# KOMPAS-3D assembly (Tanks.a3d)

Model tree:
1. Plane XY
2. Plane ZX
3. Plane ZY
4. X Axis
5. Y Axis
6. Z Axis
7. Origin
8. Polyline:1
9. Polyline:2
10. Polyline:3
11. Polyline:4
12. Polyline:5
13. Polyline:7
14. Polyline:8
15. Path 1
16. Path 2
17. Path 3
18. Path 4  (labels: C:\Program Files\ASCON\KOMPAS-3D V10\Sys\graphic.lyt)

Referenced files in C:\Program Files\ASCON\KOMPAS-3D V10\Libs\Piping\Models\Tanks\: Tank 2.a3d, Tank 1.a3d, Piping_Joint_150_1000.m3d, Piping_Flange_150_1000.m3d, Piping_Joint_50_1000.m3d, Piping_Flange_50_1000.m3d, Valve_150.a3d, Valve_50.a3d, Piping_TBend_150_1000.m3d, Piping_Transfer_50_150_1000.m3d, Piping_Bend_150_1000.m3d, Piping_Bend_50_1000.m3d, Piping_TBend_50_1000.m3d, Piping_C_Pipe_50_100035.m3d, Piping_C_Pipe_50_100036.m3d, Piping_C_Pipe_50_100037.m3d, Piping_C_Pipe_50_100038.m3d, Piping_C_Pipe_50_100039.m3d, Piping_C_Pipe_50_100040.m3d, Piping_C_Pipe_50_100041.m3d, Piping_C_Pipe_50_100042.m3d, Piping_C_Pipe_50_100043.m3d, Piping_C_Pipe_50_100044.m3d, Piping_C_Pipe_50_100045.m3d, Piping_C_Pipe_50_100046.m3d, Piping_C_Pipe_50_100047.m3d, Piping_C_Pipe_150_100048.m3d, Piping_C_Pipe_150_100049.m3d, Piping_C_Pipe_150_100050.m3d, Piping_C_Pipe_150_100051.m3d, Piping_C_Pipe_150_100052.m3d, Piping_C_Pipe_150_100053.m3d, Piping_C_Pipe_150_100054.m3d, Piping_C_Pipe_150_100055.m3d, Piping_C_Pipe_150_100056.m3d, Piping_C_Pipe_150_100057.m3d
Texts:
  Three Point Plane
  Plane at Angle
  Line and Point Plane
  Axis through Two Vertices
  Axis of Feature
  Axis of Conical Surface
  Axis through Edge
  Trim by Surface
  Trim by Sketch
  Intersection Axis of Two Planes
  Two Line Plane
  Line and Face Plane
  Pattern by Sample
  Point in CM
  Feature with No History
  Linear Dimension from Line to Point
  Surface Finish Symbol
  Geometric Tolerance Symbol
  Текст на чертеже
  Линия-выноска #1
  Линия-выноска #2
  Линия-выноска #3
  Отклонения формы и база
  Марка координационной оси
  Марка/позиционное обозначение с линией-выноской
  Марка/позиционное обозначение на линии
  Марка/позиционное обозначение без линии-выноски
  Steel ASTM A295
  Прокладка Dy 50
  Труба Dy 150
